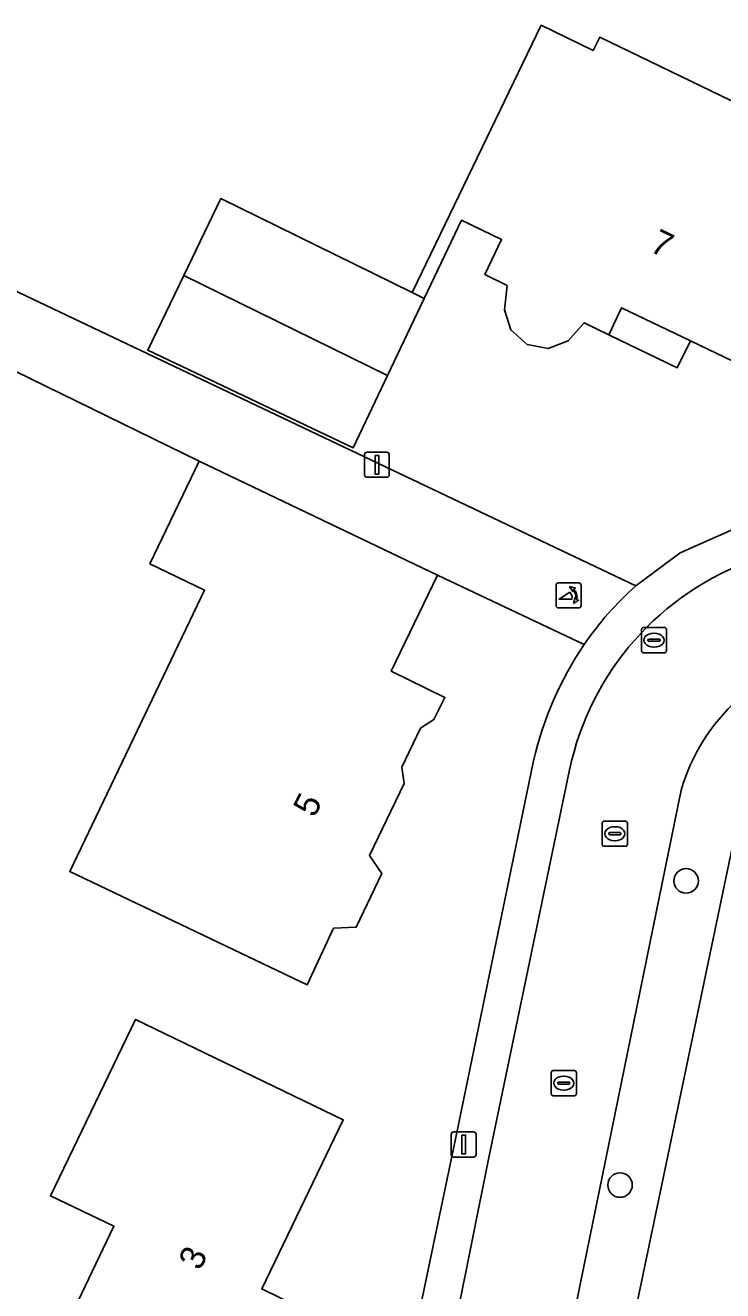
# Model space of a CAD drawing. Extents: x 163426 to 164192, y 380329 to 381641.
# Drawn here: x 163730.7 to 163758.5, y 381547.8 to 381598.3 of the extents above; entities that cross this region are included whole.
import ezdxf

# ---------------------------------------------------------------- set-up
doc = ezdxf.new("R2010")
doc.units = 0
for name, color, linetype in [('IMGEO_Boom', 7, 'Continuous'), ('IMGEO_Erf', 7, 'Continuous'), ('IMGEO_Fietspad_open', 7, 'Continuous'), ('IMGEO_Kolk', 7, 'Continuous'), ('IMGEO_Lichtmast', 7, 'Continuous'), ('IMGEO_Pand', 7, 'Continuous'), ('IMGEO_Pand_nummerreeks', 7, 'Continuous'), ('IMGEO_Pand_overbouw', 7, 'Continuous'), ('IMGEO_Poller', 7, 'Continuous'), ('IMGEO_Rijbaan_lokaal_open', 7, 'Continuous'), ('IMGEO_Rioolput', 7, 'Continuous'), ('IMGEO_Voetpad_open', 7, 'Continuous')]:
    doc.layers.add(name, color=color, linetype=linetype)

msp = doc.modelspace()

# ---------------------------------------------------------------- linework, layer by layer
at = {"layer": 'IMGEO_Boom'}
for centre in [(163757.03, 381564.177), (163754.394, 381552.048)]:
    msp.add_circle(centre, 0.489, dxfattribs=at)
at = {"layer": 'IMGEO_Erf'}
for points in [[(163761.942, 381583.432), (163757.2, 381585.708), (163754.449, 381587.029), (163753.943, 381585.948), (163752.966, 381586.43), (163752.333, 381585.705), (163751.533, 381585.402), (163750.698, 381585.569), (163750.041, 381586.152), (163749.793, 381586.945), (163749.888, 381587.914), (163748.998, 381588.362), (163749.67, 381589.749), (163748.071, 381590.522), (163746.585, 381587.398), (163745.126, 381584.33), (163743.755, 381581.447), (163735.562, 381585.345), (163736.996, 381588.314), (163738.478, 381591.382), (163746.108, 381587.632), (163747.604, 381590.748), (163751.249, 381598.292), (163753.32, 381597.282), (163753.584, 381597.822), (163761.226, 381594.122)], [(163725.547, 381589.952), (163755.022, 381575.94), (163756.795, 381577.259), (163759.731, 381578.558), (163762.978, 381579.503), (163775.299, 381582.632)], [(163752.964, 381573.6), (163747.116, 381576.372), (163745.27, 381572.545), (163747.414, 381571.491), (163746.975, 381570.605), (163746.443, 381570.271), (163745.698, 381568.706), (163745.783, 381568.065), (163744.402, 381565.194), (163744.893, 381564.465), (163743.88, 381562.327), (163742.972, 381562.29), (163741.917, 381560.027), (163732.463, 381564.545), (163737.829, 381575.773), (163735.649, 381576.816), (163737.608, 381580.916), (163724.779, 381587.18), (163711.568, 381521.785), (163709.885, 381513.746), (163716.69, 381510.952)], [(163746.337, 381546.697), (163747.877, 381554.072), (163750.947, 381568.969)], [(163759.236, 381567.28), (163754.876, 381546.411), (163794.675, 381527.159), (163809.84, 381547.27)]]:
    msp.add_lwpolyline(points, dxfattribs=at)
for points in [[(163736.996, 381588.314), (163735.562, 381585.345), (163743.755, 381581.447), (163745.126, 381584.33)], [(163738.997, 381539.779), (163733.944, 381542.205), (163730.967, 381543.634), (163731.92, 381545.62), (163734.214, 381550.402), (163731.683, 381551.616), (163735.071, 381558.643), (163743.359, 381554.647), (163740.109, 381547.903), (163741.465, 381547.249), (163740.466, 381545.178), (163741.366, 381544.744)]]:
    msp.add_lwpolyline(points, close=True, dxfattribs=at)
msp.add_arc((163764.225, 381565.941), 13.619, 145.7778, 167.1518, dxfattribs=at)
at = {"layer": 'IMGEO_Fietspad_open'}
for points in [[(163755.022, 381575.94), (163725.547, 381589.952), (163724.765, 381590.361), (163723.888, 381590.82)], [(163723.556, 381587.606), (163724.779, 381587.18), (163737.608, 381580.916), (163747.116, 381576.372), (163752.964, 381573.6)]]:
    msp.add_lwpolyline(points, dxfattribs=at)
msp.add_arc((163763.485, 381566.422), 12.736, 131.6415, 145.6961, dxfattribs=at)
at = {"layer": 'IMGEO_Kolk'}
for p, q in [((163753.687, 381565.632), (163753.687, 381566.484)), ((163753.762, 381566.558), (163754.614, 381566.558)), ((163754.175, 381566.338), (163754.2, 381566.338)), ((163754.688, 381566.484), (163754.688, 381565.632)), ((163753.946, 381566.052), (163753.946, 381566.064)), ((163754.384, 381566.015), (163753.986, 381566.015)), ((163753.989, 381566.101), (163754.387, 381566.101)), ((163754.198, 381565.778), (163754.173, 381565.778)), ((163754.43, 381566.064), (163754.43, 381566.052)), ((163754.614, 381565.558), (163753.762, 381565.558)), ((163751.727, 381556.611), (163752.579, 381556.611)), ((163751.652, 381555.685), (163751.652, 381556.537)), ((163751.911, 381556.105), (163751.911, 381556.117)), ((163751.954, 381556.154), (163752.352, 381556.154)), ((163752.14, 381556.391), (163752.165, 381556.391)), ((163752.395, 381556.117), (163752.395, 381556.105)), ((163752.653, 381556.537), (163752.653, 381555.685)), ((163752.579, 381555.611), (163751.727, 381555.611)), ((163752.349, 381556.068), (163751.951, 381556.068)), ((163752.163, 381555.831), (163752.138, 381555.831))]:
    msp.add_line(p, q, dxfattribs=at)
for points in [[(163753.687, 381565.632), (163753.687, 381566.484)], [(163753.762, 381566.558), (163754.614, 381566.558)], [(163754.688, 381566.484), (163754.688, 381565.632)], [(163754.614, 381565.558), (163753.762, 381565.558)], [(163751.727, 381556.611), (163752.579, 381556.611)], [(163751.652, 381555.685), (163751.652, 381556.537)], [(163752.653, 381556.537), (163752.653, 381555.685)], [(163752.579, 381555.611), (163751.727, 381555.611)]]:
    msp.add_lwpolyline(points, dxfattribs=at)
for centre, radius, start, end in [((163753.764, 381566.482), 0.0765, 91.552, 178.448), ((163753.764, 381566.482), 0.0765, 91.552, 178.448), ((163754.612, 381566.482), 0.0765, 1.552, 88.448), ((163754.612, 381566.482), 0.0765, 1.552, 88.448), ((163753.986, 381566.061), 0.0403, 85.8775, 175.7526), ((163753.983, 381566.051), 0.0366, 178.938, 274.7102), ((163754.387, 381566.058), 0.043, 264.8664, 352.4533), ((163754.391, 381566.063), 0.0386, 1.7309, 96.639), ((163753.764, 381565.634), 0.0765, 181.552, 268.448), ((163753.764, 381565.634), 0.0765, 181.552, 268.448), ((163754.612, 381565.634), 0.0765, 271.552, 358.448), ((163754.612, 381565.634), 0.0765, 271.552, 358.448), ((163751.729, 381556.535), 0.0765, 91.552, 178.448), ((163751.729, 381556.535), 0.0765, 91.552, 178.448), ((163752.577, 381556.535), 0.0765, 1.552, 88.448), ((163752.577, 381556.535), 0.0765, 1.552, 88.448), ((163751.951, 381556.114), 0.0403, 85.8775, 175.7526), ((163751.948, 381556.104), 0.0366, 178.938, 274.7102), ((163752.352, 381556.111), 0.043, 264.8664, 352.4533), ((163752.356, 381556.116), 0.0386, 1.7309, 96.639), ((163751.729, 381555.687), 0.0765, 181.552, 268.448), ((163751.729, 381555.687), 0.0765, 181.552, 268.448), ((163752.577, 381555.687), 0.0765, 271.552, 358.448), ((163752.577, 381555.687), 0.0765, 271.552, 358.448)]:
    msp.add_arc(centre, radius, start, end, dxfattribs=at)
for centre, major_axis, ratio, start_param, end_param in [((163754.174, 381566.058), (-0.387, 0.002), 0.722429, 4.712389, 7.853982), ((163754.199, 381566.058), (-0.39, 0.002), 0.717154, 1.570796, 4.712389), ((163752.139, 381556.111), (-0.387, 0.002), 0.722429, 4.712389, 7.853982), ((163752.164, 381556.111), (-0.39, 0.002), 0.717154, 1.570796, 4.712389)]:
    msp.add_ellipse(centre, major_axis=major_axis, ratio=ratio, start_param=start_param, end_param=end_param, dxfattribs=at)
at = {"layer": 'IMGEO_Lichtmast'}
for p, q in [((163744.205, 381580.368), (163744.205, 381581.168)), ((163744.205, 381581.168), (163744.205, 381580.368)), ((163744.305, 381581.268), (163745.095, 381581.268)), ((163745.095, 381581.268), (163744.305, 381581.268)), ((163745.195, 381581.168), (163745.195, 381580.368)), ((163745.195, 381580.368), (163745.195, 381581.168)), ((163745.095, 381580.268), (163744.305, 381580.268)), ((163744.305, 381580.268), (163745.095, 381580.268)), ((163747.765, 381554.166), (163748.555, 381554.166)), ((163748.555, 381554.166), (163747.765, 381554.166)), ((163747.665, 381553.266), (163747.665, 381554.066)), ((163747.665, 381554.066), (163747.665, 381553.266)), ((163748.655, 381554.066), (163748.655, 381553.266)), ((163748.655, 381553.266), (163748.655, 381554.066)), ((163748.555, 381553.166), (163747.765, 381553.166)), ((163747.765, 381553.166), (163748.555, 381553.166))]:
    msp.add_line(p, q, dxfattribs=at)
for points in [[(163744.625, 381581.143), (163744.775, 381581.143), (163744.775, 381580.393), (163744.625, 381580.393), (163744.625, 381581.143)], [(163748.085, 381554.041), (163748.235, 381554.041), (163748.235, 381553.291), (163748.085, 381553.291), (163748.085, 381554.041)]]:
    msp.add_lwpolyline(points, dxfattribs=at)
for centre, start, end in [((163744.305, 381581.168), 90, 180), ((163744.305, 381581.168), 90, 180), ((163745.095, 381581.168), 0, 90), ((163745.095, 381581.168), 360, 90), ((163744.305, 381580.368), 180, 270), ((163744.305, 381580.368), 180, 270), ((163745.095, 381580.368), 270, 0), ((163745.095, 381580.368), 270, 0), ((163747.765, 381554.066), 90, 180), ((163747.765, 381554.066), 90, 180), ((163748.555, 381554.066), 0, 90), ((163748.555, 381554.066), 360, 90), ((163747.765, 381553.266), 180, 270), ((163747.765, 381553.266), 180, 270), ((163748.555, 381553.266), 270, 0), ((163748.555, 381553.266), 270, 0)]:
    msp.add_arc(centre, 0.1, start, end, dxfattribs=at)
at = {"layer": 'IMGEO_Pand'}
msp.add_lwpolyline([(163761.226, 381594.122), (163753.584, 381597.822), (163753.32, 381597.282), (163751.249, 381598.292), (163747.604, 381590.748), (163746.108, 381587.632), (163746.585, 381587.398), (163748.071, 381590.522), (163749.67, 381589.749), (163748.998, 381588.362), (163749.888, 381587.914), (163749.793, 381586.945), (163750.041, 381586.152), (163750.698, 381585.569), (163751.533, 381585.402), (163752.333, 381585.705), (163752.966, 381586.43), (163753.943, 381585.948), (163754.449, 381587.029), (163757.2, 381585.708), (163761.942, 381583.432)], dxfattribs=at)
for points in [[(163738.478, 381591.382), (163736.996, 381588.314), (163745.126, 381584.33), (163746.585, 381587.398), (163746.108, 381587.632)], [(163747.116, 381576.372), (163737.608, 381580.916), (163735.649, 381576.816), (163737.829, 381575.773), (163732.463, 381564.545), (163741.917, 381560.027), (163742.972, 381562.29), (163743.88, 381562.327), (163744.893, 381564.465), (163744.402, 381565.194), (163745.783, 381568.065), (163745.698, 381568.706), (163746.443, 381570.271), (163746.975, 381570.605), (163747.414, 381571.491), (163745.27, 381572.545)], [(163743.359, 381554.647), (163735.071, 381558.643), (163731.683, 381551.616), (163734.214, 381550.402), (163731.92, 381545.62), (163730.967, 381543.634), (163733.944, 381542.205), (163738.997, 381539.779), (163741.366, 381544.744), (163740.466, 381545.178), (163741.465, 381547.249), (163740.109, 381547.903)]]:
    msp.add_lwpolyline(points, close=True, dxfattribs=at)
at = {"layer": 'IMGEO_Pand_overbouw'}
msp.add_lwpolyline([(163753.943, 381585.948), (163756.67, 381584.637), (163757.2, 381585.708), (163754.449, 381587.029)], close=True, dxfattribs=at)
at = {"layer": 'IMGEO_Poller'}
for p, q in [((163751.843, 381575.962), (163751.843, 381575.155)), ((163751.843, 381575.962), (163751.843, 381575.155)), ((163752.745, 381576.057), (163751.937, 381576.057)), ((163752.745, 381576.057), (163751.937, 381576.057)), ((163752.839, 381575.155), (163752.839, 381575.962)), ((163752.839, 381575.155), (163752.839, 381575.962)), ((163751.937, 381575.06), (163752.745, 381575.06)), ((163751.937, 381575.06), (163752.745, 381575.06))]:
    msp.add_line(p, q, dxfattribs=at)
for points in [[(163752.522, 381575.786), (163752.51, 381575.713), (163752.385, 381575.918)], [(163752.385, 381575.918), (163752.616, 381575.852), (163752.545, 381575.82)], [(163752.478, 381575.413), (163751.965, 381575.413), (163752.395, 381575.688)], [(163752.538, 381575.241), (163752.604, 381575.472), (163752.634, 381575.404)], [(163752.67, 381575.377), (163752.742, 381575.366), (163752.538, 381575.241)]]:
    msp.add_lwpolyline(points, dxfattribs=at)
for centre, radius, start, end in [((163751.937, 381575.962), 0.0946, 90, 180), ((163751.937, 381575.962), 0.0946, 90, 180), ((163752.164, 381575.473), 0.476, 351.7527, 41.1691), ((163752.164, 381575.473), 0.516, 349.3569, 42.2912), ((163752.745, 381575.962), 0.0946, 0, 90), ((163752.745, 381575.962), 0.0946, 0, 90), ((163752.15, 381575.463), 0.332, 351.3247, 42.4854), ((163751.937, 381575.155), 0.0946, 180, 270), ((163751.937, 381575.155), 0.0946, 180, 270), ((163752.745, 381575.155), 0.0946, 270, 0), ((163752.745, 381575.155), 0.0946, 270, 0)]:
    msp.add_arc(centre, radius, start, end, dxfattribs=at)
at = {"layer": 'IMGEO_Rijbaan_lokaal_open'}
for points in [[(163752.383, 381568.6), (163749.155, 381553.084), (163747.898, 381546.862)], [(163752.306, 381545.321), (163752.684, 381547.494), (163756.834, 381567.791)]]:
    msp.add_lwpolyline(points, dxfattribs=at)
for centre, radius, start, end in [((163763.512, 381566.26), 11.372, 109.2784, 168.124), ((163764.219, 381565.682), 7.68, 99.9592, 164.0644)]:
    msp.add_arc(centre, radius, start, end, dxfattribs=at)
at = {"layer": 'IMGEO_Rioolput'}
for p, q in [((163755.323, 381574.274), (163756.175, 381574.274)), ((163755.248, 381573.348), (163755.248, 381574.2)), ((163755.507, 381573.768), (163755.507, 381573.78)), ((163755.55, 381573.817), (163755.948, 381573.817)), ((163755.736, 381574.054), (163755.761, 381574.054)), ((163755.991, 381573.78), (163755.991, 381573.768)), ((163756.249, 381574.2), (163756.249, 381573.348)), ((163756.175, 381573.274), (163755.323, 381573.274)), ((163755.945, 381573.731), (163755.547, 381573.731)), ((163755.759, 381573.494), (163755.734, 381573.494))]:
    msp.add_line(p, q, dxfattribs=at)
for points in [[(163755.323, 381574.274), (163756.175, 381574.274)], [(163755.248, 381573.348), (163755.248, 381574.2)], [(163756.249, 381574.2), (163756.249, 381573.348)], [(163756.175, 381573.274), (163755.323, 381573.274)]]:
    msp.add_lwpolyline(points, dxfattribs=at)
for centre, radius, start, end in [((163755.325, 381574.198), 0.0765, 91.552, 178.448), ((163755.325, 381574.198), 0.0765, 91.552, 178.448), ((163756.173, 381574.198), 0.0765, 1.552, 88.448), ((163756.173, 381574.198), 0.0765, 1.552, 88.448), ((163755.547, 381573.777), 0.0403, 85.8775, 175.7526), ((163755.544, 381573.767), 0.0366, 178.938, 274.7102), ((163755.948, 381573.774), 0.043, 264.8664, 352.4533), ((163755.952, 381573.779), 0.0386, 1.7309, 96.639), ((163755.325, 381573.35), 0.0765, 181.552, 268.448), ((163755.325, 381573.35), 0.0765, 181.552, 268.448), ((163756.173, 381573.35), 0.0765, 271.552, 358.448), ((163756.173, 381573.35), 0.0765, 271.552, 358.448)]:
    msp.add_arc(centre, radius, start, end, dxfattribs=at)
for centre, major_axis, ratio, start_param, end_param in [((163755.735, 381573.774), (-0.387, 0.002), 0.722429, 4.712389, 7.853982), ((163755.76, 381573.774), (-0.39, 0.002), 0.717154, 1.570796, 4.712389)]:
    msp.add_ellipse(centre, major_axis=major_axis, ratio=ratio, start_param=start_param, end_param=end_param, dxfattribs=at)
at = {"layer": 'IMGEO_Voetpad_open'}
for points in [[(163775.299, 381582.632), (163762.978, 381579.503), (163759.731, 381578.558), (163756.795, 381577.259), (163755.022, 381575.94)], [(163750.947, 381568.969), (163747.877, 381554.072), (163746.337, 381546.697)], [(163747.898, 381546.862), (163749.155, 381553.084), (163752.383, 381568.6)], [(163756.834, 381567.791), (163752.684, 381547.494), (163752.306, 381545.321)], [(163754.63, 381545.233), (163754.876, 381546.411), (163759.236, 381567.28)]]:
    msp.add_lwpolyline(points, dxfattribs=at)
for centre, radius, start, end in [((163763.512, 381566.26), 11.372, 109.2784, 168.124), ((163763.485, 381566.422), 12.736, 131.6415, 145.6961), ((163764.225, 381565.941), 13.619, 145.7778, 167.1518), ((163764.219, 381565.682), 7.68, 99.9592, 164.0644)]:
    msp.add_arc(centre, radius, start, end, dxfattribs=at)

# ---------------------------------------------------------------- texts
at = {"layer": 'IMGEO_Pand_nummerreeks'}
for s, rotation, p in [('7', 334.3544, (163755.53, 381589.306)), ('5', 63.6423, (163742.212, 381566.666)), ('3', 64.2687, (163737.65, 381548.605))]:
    msp.add_text(s, height=1, rotation=rotation, dxfattribs=at).set_placement(p)

doc.saveas('drawing.dxf')
